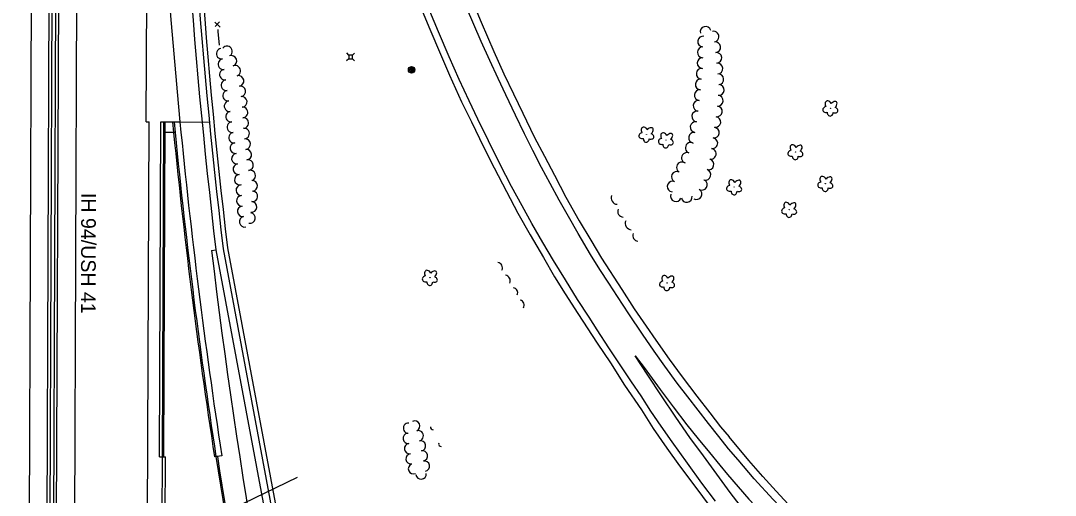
# Model space of a CAD drawing. Extents: x 588843 to 2552415, y 180129 to 269402.
# Drawn here: x 593995 to 594701, y 186692 to 187016 of the extents above; entities that cross this region are included whole.
import ezdxf

# ---------------------------------------------------------------- set-up
doc = ezdxf.new("R2010")
doc.units = 0
for name, color, linetype in [('Default', 7, 'Continuous'), ('E_DRN', 7, 'Continuous'), ('E_FEN_P', 7, 'Continuous'), ('E_LAND_TreeLine_P', 7, 'Continuous'), ('E_LAND_Vegetation', 7, 'Continuous'), ('E_MISCPROP', 7, 'Continuous'), ('E_RDWY', 7, 'Continuous'), ('E_RDWY_Gravel', 7, 'Continuous'), ('E_RDWY_Text', 7, 'Continuous'), ('E_UTL_AG_Bold', 7, 'Continuous'), ('P_DRN_SS_UG', 7, 'Continuous'), ('P_RDWY_BarrierConc', 7, 'Continuous'), ('P_RDWY_C_and_G', 7, 'Continuous'), ('P_RDWY_C_and_GBack', 7, 'Continuous'), ('P_RDWY_C_and_GFace', 7, 'Continuous'), ('P_RDWY_LaneEdge', 7, 'Continuous'), ('P_RDWY_PavtEdge', 7, 'Continuous'), ('P_RDWY_ShldAgg', 7, 'Continuous'), ('P_RDWY_ShldPaved', 7, 'Continuous')]:
    doc.layers.add(name, color=color, linetype=linetype)

# ---------------------------------------------------------------- blocks, each defined once
blk = doc.blocks.new('CULV2')
at = {"layer": 'E_DRN'}
blk.add_arc((19.7, 14.8), 24.6, 216.8699, 323.1301, dxfattribs=at)
blk = doc.blocks.new('DTRE')
at = {"layer": 'Default'}
blk.add_circle((-0.2, 0), 0.183, dxfattribs=at)
for centre, major_axis, ratio in [((-5.9, 0.2), (4.93, -0.12), 0.832022), ((-1.9, 5.3), (1.36, -4.98), 0.782863), ((4.1, 2.7), (-5.27, -2.93), 0.691916), ((-2.5, -5.2), (1.8, 4.86), 0.716896), ((3.5, -3.7), (-5.01, 4.58), 0.560249)]:
    blk.add_ellipse(centre, major_axis=major_axis, ratio=ratio, start_param=1.570796, end_param=4.712389, dxfattribs=at)
blk = doc.blocks.new('POLE')
at = {"layer": 'Default'}
for radius in [4.46, 3.35, 2.23, 1.12]:
    blk.add_circle((0, 0), radius, dxfattribs=at)
blk = doc.blocks.new('PED')
at = {"layer": 'Default'}
for p, q in [((-2.5, 2.5), (-5.3, 5.3)), ((2.5, 2.5), (5.3, 5.3)), ((-2.5, -2.5), (-5.3, -5.3)), ((2.5, -2.5), (5.3, -5.3))]:
    blk.add_line(p, q, dxfattribs=at)
blk.add_lwpolyline([(-2.5, -2.5), (2.5, -2.5), (2.5, 2.5), (-2.5, 2.5)], close=True, dxfattribs=at)

msp = doc.modelspace()

# ---------------------------------------------------------------- linework, layer by layer
at = {"layer": 'E_FEN_P'}
for p, q in [((594127.28, 187015.15), (594130.98, 187011.72)), ((594130.59, 187015.33), (594127.67, 187012.14))]:
    msp.add_line(p, q, dxfattribs=at)
msp.add_lwpolyline([(594129.34, 187010.25), (594129.49, 187008.83), (594130.37, 186999.36)], dxfattribs=at)
at = {"layer": 'E_LAND_TreeLine_P'}
for centre, radius, start, end in [((594462.1, 187008.54), 3.66, 15.01895, 195.01895), ((594467.48, 187005.29), 3.66, 280.31259, 100.31259), ((594460.42, 187001.9), 3.66, 82.53972, 262.53972), ((594468.68, 186998.07), 3.66, 275.82973, 95.82973), ((594132.03, 186993.64), 3.62, 98.59861, 278.59861), ((594135.57, 186995.22), 3.62, 321.15114, 141.15114), ((594460.2, 186994.58), 3.66, 88.79876, 268.79876), ((594133.11, 186986.49), 3.62, 98.59861, 278.59861), ((594138.67, 186988.71), 3.62, 290.66112, 110.66112), ((594460.05, 186987.26), 3.66, 88.79876, 268.79876), ((594469.43, 186990.78), 3.66, 275.82973, 95.82973), ((594134.19, 186979.33), 3.62, 98.59861, 278.59861), ((594141.25, 186981.95), 3.62, 291.06903, 111.06903), ((594459.44, 186979.96), 3.66, 84.91202, 264.91202), ((594470.13, 186983.48), 3.66, 274.6812, 94.6812), ((594135.27, 186972.17), 3.62, 98.59861, 278.59861), ((594143.49, 186975.09), 3.62, 279.58306, 99.58306), ((594458.79, 186972.66), 3.66, 84.91202, 264.91202), ((594470.73, 186976.18), 3.66, 274.6812, 94.6812), ((594136.36, 186965.01), 3.62, 98.59861, 278.59861), ((594144.69, 186967.95), 3.62, 279.58306, 99.58306), ((594458.14, 186965.36), 3.66, 83.32966, 263.32966), ((594471, 186968.88), 3.66, 265.31549, 85.31549), ((594137.4, 186957.85), 3.62, 97.92545, 277.92545), ((594145.7, 186960.79), 3.62, 277.92377, 97.92377), ((594457.29, 186958.08), 3.66, 83.32966, 263.32966), ((594470.4, 186961.57), 3.66, 265.31549, 85.31549), ((594138.39, 186950.68), 3.62, 97.92545, 277.92545), ((594146.24, 186953.57), 3.62, 274.02522, 94.02522), ((594456.37, 186950.81), 3.66, 81.35504, 261.35504), ((594469.75, 186954.28), 3.66, 262.19392, 82.19392), ((594139.39, 186943.51), 3.62, 97.92545, 277.92545), ((594146.75, 186946.35), 3.62, 274.02522, 94.02522), ((594455.27, 186943.57), 3.66, 81.35504, 261.35504), ((594468.76, 186947.02), 3.66, 262.19392, 82.19392), ((594140.39, 186936.34), 3.62, 97.92545, 277.92545), ((594147.26, 186939.12), 3.62, 274.02522, 94.02522), ((594454.17, 186936.32), 3.66, 81.35504, 261.35504), ((594467.76, 186939.76), 3.66, 262.19392, 82.19392), ((594141.39, 186929.17), 3.62, 98.03137, 278.03137), ((594147.97, 186931.92), 3.62, 276.60775, 96.60775), ((594451.93, 186929.37), 3.66, 69.4824, 249.4824), ((594466.69, 186932.51), 3.66, 261.44638, 81.44638), ((594142.4, 186922), 3.62, 98.03137, 278.03137), ((594148.8, 186924.73), 3.62, 276.60775, 96.60775), ((594449.36, 186922.51), 3.66, 69.4824, 249.4824), ((594465.6, 186925.26), 3.66, 261.44638, 81.44638), ((594143.41, 186914.83), 3.62, 98.03137, 278.03137), ((594149.96, 186917.59), 3.62, 279.88133, 99.88133), ((594445.91, 186916.06), 3.66, 60.76759, 240.76759), ((594464.08, 186918.11), 3.66, 253.68304, 73.68304), ((594144.42, 186907.66), 3.62, 98.03137, 278.03137), ((594151.52, 186910.54), 3.62, 289.65322, 109.65322), ((594442.44, 186909.6), 3.66, 63.47907, 243.47907), ((594462.02, 186911.08), 3.66, 253.68304, 73.68304), ((594145.4, 186900.49), 3.62, 93.15573, 273.15573), ((594152.88, 186903.49), 3.62, 274.50935, 94.50935), ((594439.56, 186902.96), 3.66, 84.18811, 264.18811), ((594459.59, 186904.2), 3.66, 239.81905, 59.81905), ((594145.8, 186893.26), 3.62, 93.15573, 273.15573), ((594152.92, 186896.28), 3.62, 265.00486, 85.00486), ((594441.87, 186896.41), 3.66, 159.35872, 339.35872), ((594449.23, 186895.84), 3.66, 189.90259, 9.90259), ((594455.91, 186897.87), 3.66, 239.81905, 59.81905), ((594146.38, 186886.05), 3.62, 96.44377, 276.44377), ((594152.29, 186889.07), 3.62, 265.00486, 85.00486), ((594147.7, 186878.94), 3.62, 102.62081, 282.62081), ((594151.27, 186881.53), 3.62, 259.54535, 79.54535), ((594259.43, 186738.13), 3.52, 84.98468, 264.98468), ((594263.69, 186739.54), 3.52, 294.46395, 114.46395), ((594259.25, 186731.13), 3.52, 97.85155, 277.85155), ((594266.1, 186732.95), 3.52, 287.75694, 107.75694), ((594260.21, 186724.16), 3.52, 97.85155, 277.85155), ((594267.59, 186726.08), 3.52, 281.05915, 101.05915), ((594261.17, 186717.2), 3.52, 97.85155, 277.85155), ((594268.94, 186719.18), 3.52, 281.05915, 101.05915), ((594262.84, 186710.43), 3.52, 113.44553, 293.44553), ((594270.29, 186712.27), 3.52, 281.05915, 101.05915), ((594268.05, 186706.82), 3.52, 185.22751, 5.22751)]:
    msp.add_arc(centre, radius, start, end, dxfattribs=at)
at = {"layer": 'E_RDWY'}
for points in [[(594477.72, 186724.08), (594471.01, 186732.37), (594463.98, 186741.35), (594456.97, 186750.32), (594449.95, 186759.55), (594442.77, 186768.88), (594434.37, 186780.5), (594427, 186790.77), (594419.01, 186802.22), (594409.73, 186816.05), (594401.93, 186827.88), (594396.12, 186836.98), (594390, 186846.32), (594383.59, 186856.65), (594375.12, 186870.88), (594368.48, 186882.48), (594362.3, 186893.61), (594356.07, 186905), (594350.24, 186916.04), (594344.35, 186927.5), (594338.56, 186939), (594332.46, 186951.76), (594325.87, 186965.66), (594320.57, 186976.64), (594314.92, 186988.92), (594309.07, 187002.03), (594304.06, 187013.63), (594299.1, 187025.27)], [(594468.85, 186688.28), (594459.54, 186700.69), (594449.83, 186714.14), (594439.22, 186728.91), (594431.79, 186739.59), (594424.78, 186749.78), (594418.04, 186760.09), (594411.54, 186769.72), (594403.79, 186781.38), (594396.11, 186793.05), (594388.11, 186805.25), (594382.6, 186813.96), (594374.73, 186826.03), (594366.47, 186839.42), (594358.34, 186852.5), (594351.14, 186864.71), (594343.65, 186877.76), (594336.94, 186889.72), (594329.8, 186902.99), (594321.98, 186917.98), (594313.94, 186934.07), (594306.82, 186948.99), (594300.8, 186961.38), (594294.07, 186976.04), (594287.17, 186991.5), (594279.79, 187008.63), (594274.03, 187022.57)], [(594478.96, 186694.32), (594467.83, 186709.17), (594460.59, 186719.23), (594451.43, 186731.77), (594441.89, 186745.63), (594431.92, 186760.1), (594422.64, 186774.21), (594414.15, 186787.53), (594420.22, 186779.54), (594431.16, 186764.51), (594440.05, 186752.71), (594449.34, 186740.45), (594456.98, 186730.95), (594464.77, 186721.42), (594471.74, 186712.84), (594477.14, 186706.52)], [(594694.85, 186504.49), (594683.62, 186515.53), (594672.83, 186525.93), (594662.5, 186536), (594651.76, 186546.32), (594637.55, 186559.85), (594626.71, 186570.53), (594615.5, 186581.26), (594604.84, 186591.47), (594593.79, 186602.23), (594581.91, 186613.87), (594572.39, 186623.47), (594562.73, 186633.03), (594551.71, 186644.15), (594542.03, 186654.09), (594532.72, 186663.69), (594520.2, 186676.64), (594508.28, 186689.46), (594495.3, 186703.63), (594484.27, 186716.42), (594477.72, 186724.08)], [(594477.14, 186706.52), (594491.64, 186689.79), (594507.32, 186673.09), (594524.78, 186655.05), (594546.18, 186633.28), (594564.99, 186614.76), (594590.8, 186589.1), (594599.31, 186580.87), (594588.82, 186569.53), (594568.94, 186589.83), (594547.19, 186612.37), (594532.99, 186627.6), (594518.36, 186644.35), (594506.5, 186658.74), (594494.07, 186674.48), (594478.96, 186694.32)]]:
    msp.add_lwpolyline(points, dxfattribs=at)
at = {"layer": 'E_RDWY_Gravel'}
for points in [[(594302.04, 187032.27), (594309.03, 187015.2), (594317.69, 186995.22), (594324.51, 186979.94), (594331.01, 186966.19), (594337.33, 186953.07), (594345.17, 186936.99), (594352.11, 186923.78), (594358.93, 186910.7), (594366.82, 186895.78), (594375.87, 186879.7), (594383.75, 186866.45), (594391.09, 186854.1), (594404.98, 186832.7), (594413.4, 186819.64), (594421.48, 186807.72), (594428.25, 186798.26), (594437.28, 186785.11), (594446.14, 186773.18), (594456.04, 186759.98), (594464.93, 186748.51), (594472.31, 186739.04), (594478.14, 186732.11)], [(594268.73, 187022.89), (594273.98, 187010.46), (594281.21, 186993.39), (594287.45, 186979.08), (594295.69, 186960.74), (594302.36, 186947.04), (594310.57, 186930.13), (594317.85, 186915.71), (594326.23, 186899.57), (594334.05, 186884.89), (594342.48, 186870.12), (594351.55, 186854.48), (594359.06, 186841.49), (594366.35, 186829.77), (594374.99, 186816.32), (594388.18, 186796.12), (594397.14, 186782.65), (594406.88, 186767.42), (594418.28, 186750.67), (594426.37, 186738), (594435.58, 186724.43), (594444.34, 186712.34), (594454.66, 186698.59), (594465.15, 186684.37)], [(594700.63, 186506.16), (594687.52, 186519.09), (594675.61, 186530.71), (594665.26, 186540.5), (594652.71, 186552.83), (594639.57, 186565.68), (594629.53, 186575.26), (594618.09, 186586.15), (594608.82, 186595.18), (594597.41, 186606.28), (594588.73, 186614.96), (594578.1, 186625.43), (594569.01, 186634.38), (594556.67, 186646.84), (594545.31, 186658.38), (594532.9, 186671.04), (594521.1, 186683.26), (594510.14, 186695.03), (594501.09, 186705.12), (594491.57, 186716.08), (594478.14, 186732.11)]]:
    msp.add_lwpolyline(points, dxfattribs=at)
at = {"layer": 'P_DRN_SS_UG'}
msp.add_line((593753.81, 186496.81), (594183.81, 186704.8), dxfattribs=at)
at = {"layer": 'P_RDWY_BarrierConc'}
for p, q in [((594012.05, 186455.23), (594017.54, 187818.59)), ((594014.05, 186455.22), (594019.54, 187818.59)), ((594016.55, 186455.21), (594022.04, 187818.58)), ((594018.55, 186455.2), (594024.04, 187818.57)), ((594089.61, 186718.68), (594093.61, 186718.66)), ((594090.55, 186454.91), (594091.61, 186718.67)), ((594092.55, 186454.9), (594093.61, 186718.66))]:
    msp.add_line(p, q, dxfattribs=at)
at = {"layer": 'P_RDWY_C_and_G'}
for p, q in [((594089.61, 186718.68), (594090.53, 186947.09)), ((594090.53, 186947.09), (594103.55, 186947.04)), ((594089.61, 186718.68), (594091.61, 186718.67)), ((594132.05, 186719.33), (594127.11, 186718.58))]:
    msp.add_line(p, q, dxfattribs=at)
msp.add_arc((598199.35, 187344.1), 4115, 185.53716, 188.73282, dxfattribs=at)
at = {"layer": 'P_RDWY_C_and_GBack'}
msp.add_line((594092.61, 186718.67), (594093.53, 186947.08), dxfattribs=at)
msp.add_arc((598199.35, 187344.1), 4120, 185.53014, 188.73282, dxfattribs=at)
at = {"layer": 'P_RDWY_C_and_GFace'}
for p, q in [((594091.61, 186718.67), (594092.53, 186947.09)), ((594092.5, 186940.09), (594100.21, 186940.05))]:
    msp.add_line(p, q, dxfattribs=at)
msp.add_arc((598199.35, 187344.1), 4119, 185.53154, 188.73282, dxfattribs=at)
at = {"layer": 'P_RDWY_LaneEdge'}
msp.add_arc((598199.35, 187344.1), 4103, 186.78408, 193.13426, dxfattribs=at)
at = {"layer": 'P_RDWY_PavtEdge'}
for p, q in [((594031.1, 186488.04), (594036.59, 187851.41)), ((594000.05, 186455.27), (594005.54, 187818.64)), ((594080.53, 186947.13), (594084.04, 187818.33)), ((594080.53, 186947.13), (594082.53, 186947.13)), ((594080.55, 186454.95), (594082.53, 186947.13)), ((594103.55, 186947.04), (594123.65, 186946.96)), ((594128.05, 186859.78), (594177.58, 186594.63))]:
    msp.add_line(p, q, dxfattribs=at)
for radius, end in [(4115, 185.53716), (4100, 186.78408)]:
    msp.add_arc((598199.35, 187344.1), radius, 180.91482, end, dxfattribs=at)
at = {"layer": 'P_RDWY_ShldAgg'}
msp.add_line((594135.92, 186861.25), (594185.45, 186596.09), dxfattribs=at)
for radius, start, end in [(4092, 180.91482, 186.77667), (4119, 188.73282, 193.13426)]:
    msp.add_arc((598199.35, 187344.1), radius, start, end, dxfattribs=at)
at = {"layer": 'P_RDWY_ShldPaved'}
for p, q in [((594125.07, 186859.42), (594128.05, 186859.78)), ((594133, 186860.53), (594182.5, 186595.54))]:
    msp.add_line(p, q, dxfattribs=at)
for radius, start, end in [(4095, 180.91482, 186.78177), (4118, 188.73282, 193.13426)]:
    msp.add_arc((598199.35, 187344.1), radius, start, end, dxfattribs=at)

# ---------------------------------------------------------------- block references
at = {"layer": 'E_DRN'}
for p, xscale, yscale, rotation in [((594398, 186896.82), 0.1780199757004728, 0.1780199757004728, -58.33256333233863), ((594402.44, 186887.65), 0.16532051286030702, 0.16532051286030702, -59.28036603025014), ((594407.6, 186879.6), 0.18313345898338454, 0.18313345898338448, -58.50925806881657), ((594412.65, 186870.84), 0.15439704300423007, 0.1543970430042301, -57.7479328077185), ((594323.19, 186845.91), 0.15237891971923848, 0.1523789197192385, 117.68533949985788), ((594328.48, 186837.15), 0.15237891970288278, 0.15237891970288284, 117.68533949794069), ((594333.61, 186829.02), 0.14210055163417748, 0.14210055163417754, 117.85336183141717), ((594337.87, 186820.16), 0.1462117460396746, 0.14621174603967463, 112.94429969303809), ((594274.52, 186739.12), 0.06754713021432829, 0.06754713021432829, -50.146428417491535), ((594280.06, 186727.93), 0.07393942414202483, 0.07393942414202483, -54.33134454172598)]:
    msp.add_blockref('CULV2', p, dxfattribs=dict(at, xscale=xscale, yscale=yscale, rotation=rotation))
at = {"layer": 'E_LAND_Vegetation', "xscale": 0.5}
for p, yscale, rotation in [((594547.23, 186956.53), 0.49999999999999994, 89.60957435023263), ((594421.8, 186938.64), 0.5, 88.79875775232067), ((594435.08, 186934.74), 0.5, 88.79875775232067), ((594523.39, 186926.68), 0.49999999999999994, 89.60957435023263), ((594543.77, 186905.05), 0.49999999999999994, 89.60957435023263), ((594481.6, 186902.77), 0.49999999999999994, 89.60957435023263), ((594519.14, 186887.35), 0.49999999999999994, 89.60957435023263), ((594274.07, 186840.92), 0.5, 88.79875775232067), ((594435.85, 186837.36), 0.5, 88.79875775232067)]:
    msp.add_blockref('DTRE', p, dxfattribs=dict(at, yscale=yscale, rotation=rotation))
at = {"layer": 'E_MISCPROP', "xscale": 0.5, "yscale": 0.5, "rotation": 88.79875775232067}
msp.add_blockref('POLE', (594261.56, 186982.57), dxfattribs=at)
at = {"layer": 'E_UTL_AG_Bold', "xscale": 0.5, "yscale": 0.5, "rotation": 88.79875775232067}
msp.add_blockref('PED', (594219.92, 186991.41), dxfattribs=at)

# ---------------------------------------------------------------- texts
at = {"layer": 'E_RDWY_Text'}
msp.add_text('IH 94/USH 41', height=10, rotation=269.84908, dxfattribs=at).set_placement((594036.2, 186898.68))

doc.saveas('drawing.dxf')
